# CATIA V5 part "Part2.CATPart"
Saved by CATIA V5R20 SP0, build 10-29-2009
Part number: Part2
Bounding box of the stored display mesh (mm): x -5 to 5, y -17.5 to 0, z -5 to 5
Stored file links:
  E:\Ehsan\Catia\Tamrin\Digital Mockup\4\Part2.CATPart
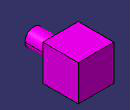
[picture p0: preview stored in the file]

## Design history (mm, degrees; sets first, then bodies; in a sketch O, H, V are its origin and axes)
Body1 (main body)
  DatumSurface1
  Sketch1 on zx-plane, origin (0, 0, 0), H (-1, 0, 0), V (0, 0, 1)
  Pad1: profile Sketch1, direction (0, -1, 0), length 10
  Sketch2 on end face of Pad1, origin (0, -10, 0), H (1, 0, 0), V (0, 0, 1)
    circle A1 centre (0, 0) radius 2.5
    radius A1 = 2.5
  Pad2: profile Sketch2, direction (0, -1, 0), length 7.5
